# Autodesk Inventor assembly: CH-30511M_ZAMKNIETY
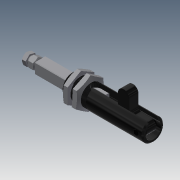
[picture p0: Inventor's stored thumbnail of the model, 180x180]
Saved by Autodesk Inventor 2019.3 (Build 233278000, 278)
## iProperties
Company: ·L?¤¤?
Created: 2010-06
Part Number: CH-30511M_ZAMKNIETY
Material: Ogólny
Description: STEP AP203
Document SubType Name: Assembly
Designer: CADENGINEERING4
Sending System: SolidWorks 2005179
Preprocessor: SwSTEP 2.0
Title: CH-30511M.STEP
Author: ·L?¥Î?
Revision Number: ANY
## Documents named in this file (12)
- D:\Vault_2016\Projekty\STRONA\Push-pull clamp\CH-30511M\CH-30511M_ZAMKNIETY.iam
- D:\Vault_2016\Projekty\STRONA\Push-pull clamp\CH-30511M\CH-30511M-01___.ipt
- D:\Vault_2016\Projekty\STRONA\Push-pull clamp\CH-30511M\CH-30510M-04___.ipt
- D:\Vault_2016\Projekty\STRONA\Push-pull clamp\CH-30511M\CH-30511M-02___.ipt
- D:\Vault_2016\Projekty\STRONA\Push-pull clamp\CH-30511M\M12___.ipt
- D:\Vault_2016\Projekty\STRONA\Push-pull clamp\CH-30511M\CH-30509-08___.ipt
- D:\Vault_2016\Projekty\STRONA\Push-pull clamp\CH-30511M\CH-30510M-03___.ipt
- D:\Vault_2016\Projekty\STRONA\Push-pull clamp\CH-30511M\CH-30509-07___.ipt
- D:\Vault_2016\Projekty\STRONA\Push-pull clamp\CH-30511M\M12X50___.ipt
- D:\Vault_2016\Projekty\STRONA\Push-pull clamp\CH-30511M\CH-30510M-02___.ipt
- D:\Vault_2016\Projekty\STRONA\Push-pull clamp\CH-30511M\CH-30509-06___.ipt
- D:\Vault_2016\Projekty\STRONA\Push-pull clamp\CH-30511M\CH-30509-09___.ipt
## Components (12 placed, 12 different names)
1. CH-30511M-01_??_1
2. CH-30510M-04_??_2
3. CH-30511M-02_??_3
4. M12_??_4
5. CH-30509-08_??_5
6. CH-30510M-03_??_6
7. CH-30509-07_??_7
8. M12X50_??_8
9. CH-30510M-02_??_9
10. CH-30511M-02_??_10
11. CH-30509-06_??_11
12. CH-30509-09_??_12
